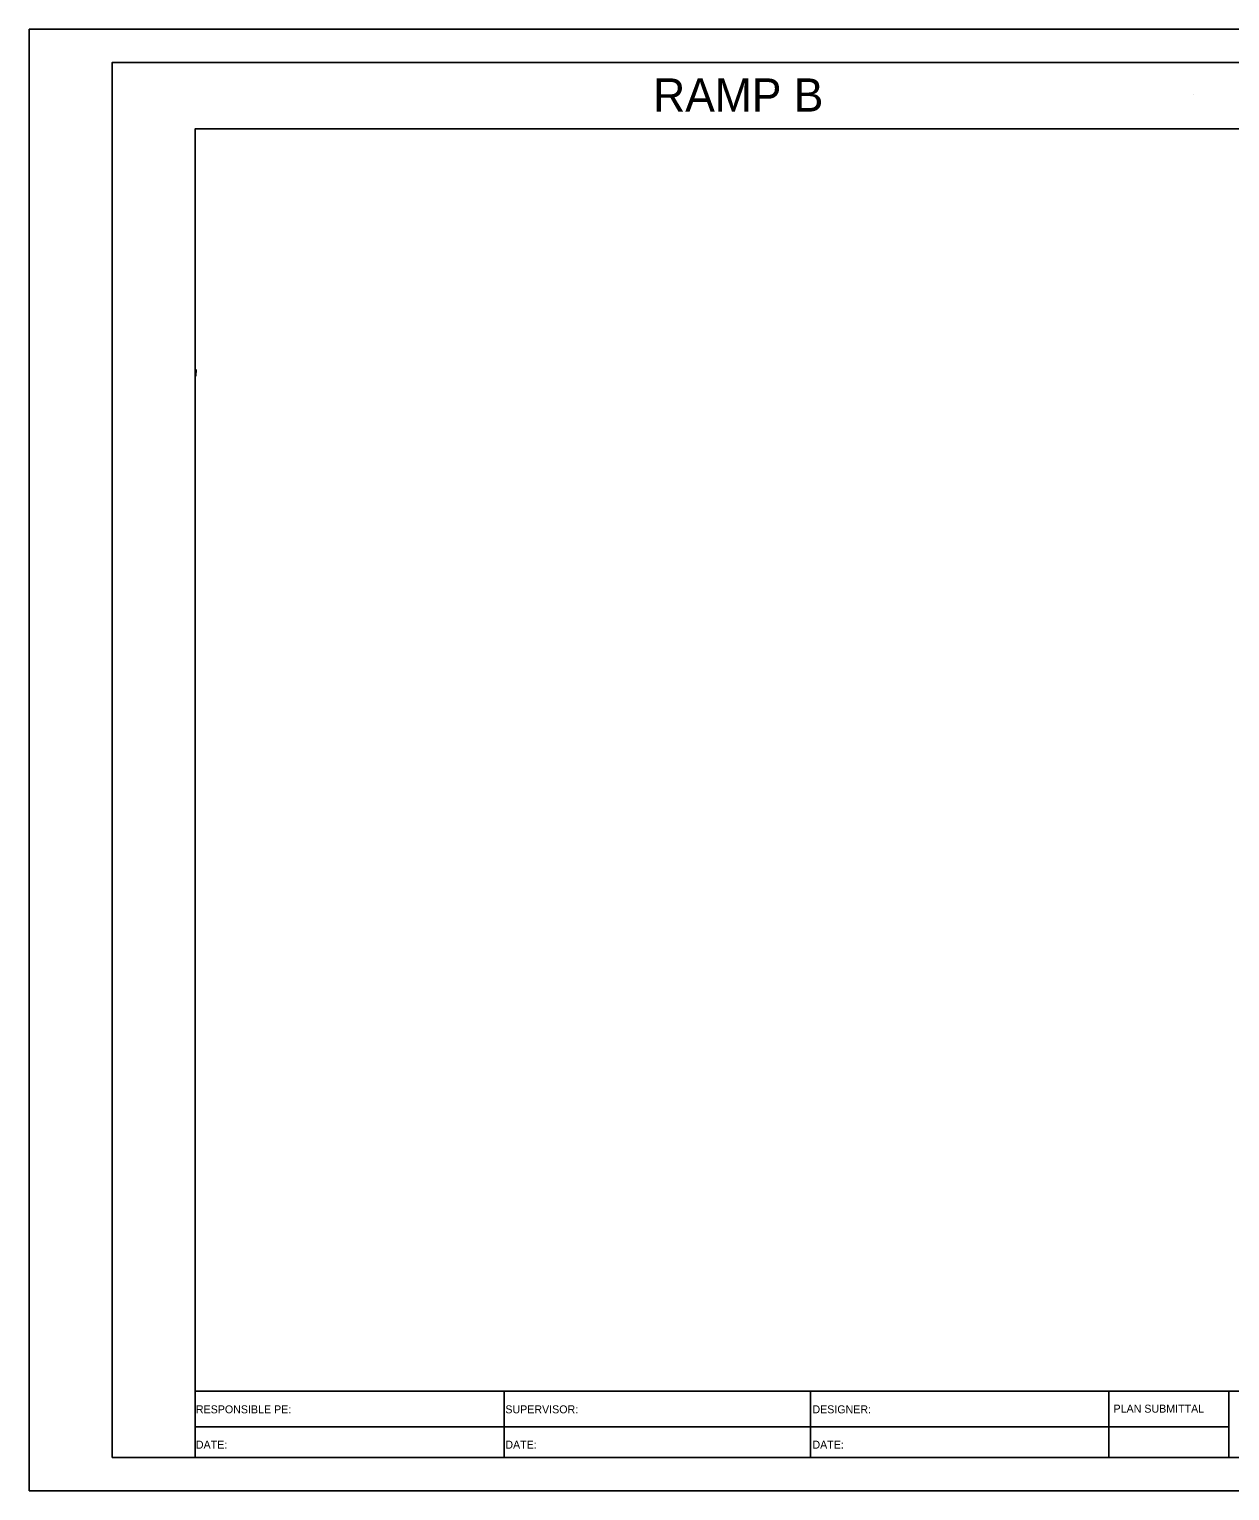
# Model space of a CAD drawing. Extents: x 1797478 to 1805176, y 246529 to 250952.
# Drawn here: x 1802116 to 1802296.8, y 250064.4 to 250284.4 of the extents above; entities that cross this region are included whole.
import ezdxf

# ---------------------------------------------------------------- set-up
doc = ezdxf.new("R2010")
doc.units = 0
for name, color, linetype in [('2', 7, 'Continuous'), ('ANNO-SHT', 7, 'Continuous'), ('ANNO-TXT', 7, 'Continuous'), ('AXIS', 7, 'Continuous'), ('DRAINAGE', 7, 'Continuous'), ('Level 1', 7, 'Continuous'), ('Level 62', 7, 'Continuous'), ('SHT-BDR', 7, 'Continuous'), ('SHT-BNDRY', 7, 'Continuous')]:
    doc.layers.add(name, color=color, linetype=linetype)

# ---------------------------------------------------------------- blocks, each defined once
blk = doc.blocks.new('SC47208')
at = {"layer": 'Level 1'}
blk.add_line((0, 0), (0, 0), dxfattribs=at)

msp = doc.modelspace()

# ---------------------------------------------------------------- linework, layer by layer
at = {"layer": '2'}
msp.add_lwpolyline([(1802141.12, 250233.21), (1802141.1, 250232.21)], dxfattribs=at)
msp.add_lwpolyline([(1802141.12, 250233.21), (1802141.1, 250232.21)], dxfattribs=at)
at = {"layer": 'AXIS'}
msp.add_line((1802141, 250189.42), (1802141, 250189.43), dxfattribs=at)
at = {"layer": 'Level 62'}
msp.add_lwpolyline([(1802116, 250064.42), (1802456, 250064.42), (1802456, 250284.42), (1802116, 250284.42)], close=True, dxfattribs=at)
at = {"layer": 'SHT-BDR'}
msp.add_lwpolyline([(1802141, 250079.43), (1802441, 250079.43), (1802441, 250269.43), (1802141, 250269.43)], close=True, dxfattribs=at)
at = {"layer": 'SHT-BNDRY'}
for p, q in [((1802141, 250069.42), (1802141, 250079.43)), ((1802187.52, 250079.43), (1802187.52, 250069.42)), ((1802233.67, 250069.42), (1802233.67, 250079.43)), ((1802278.59, 250069.42), (1802278.59, 250079.43)), ((1802296.63, 250069.42), (1802296.63, 250079.43)), ((1802141, 250074.03), (1802296.63, 250074.03))]:
    msp.add_line(p, q, dxfattribs=at)
msp.add_lwpolyline([(1802128.5, 250069.42), (1802451, 250069.42), (1802451, 250279.42), (1802128.5, 250279.42)], close=True, dxfattribs=at)

# ---------------------------------------------------------------- block references
at = {"layer": 'DRAINAGE', "xscale": 0.2, "yscale": 0.20000000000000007, "rotation": -116.41666666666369}
msp.add_blockref('SC47208', (1802291.32, 250274.62), dxfattribs=at)
msp.add_blockref('SC47208', (1802291.32, 250274.62), dxfattribs=at)

# ---------------------------------------------------------------- texts
at = {"layer": 'ANNO-SHT'}
msp.add_text('                 RAMP B                 ', height=4.9995, rotation=360, dxfattribs=at).set_placement((1802178.38, 250272.02))
at = {"layer": 'ANNO-TXT'}
for s, p in [('RESPONSIBLE PE:', (1802141.1, 250076.08)), ('SUPERVISOR:', (1802187.7, 250076.08)), ('DESIGNER:', (1802233.94, 250076.08)), ('PLAN SUBMITTAL', (1802279.28, 250076.18)), ('DATE:', (1802141.1, 250070.76)), ('DATE:', (1802187.7, 250070.76)), ('DATE:', (1802233.94, 250070.76))]:
    msp.add_text(s, height=1.2, rotation=360, dxfattribs=at).set_placement(p)

doc.saveas('drawing.dxf')
